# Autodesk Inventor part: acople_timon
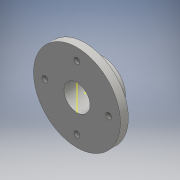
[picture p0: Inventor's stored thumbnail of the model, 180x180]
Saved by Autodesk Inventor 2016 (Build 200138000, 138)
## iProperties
Created: 2017-06
Part Number: acople_timon
Material: Generic
Document SubType Name: Modeling
Designer: laboratorioesan
Density: 1 g/cm^3
Appearance: Default
Author: laboratorioesan
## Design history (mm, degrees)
sketch "Sketch1"
  geometry: C1 r 9 at (0, 0); C2 r 15.5 at (0, 0); 1 further point
  constraints: 2 centre point, 2 coincident
  dimensions: "d0" = 18 diameter of C1; "d1" = 31 diameter of C2
extrude "Extrusion1" new body sketch "Sketch1" distance "d2" = 12.5; taper "d3" = 0 deg
sketch "Sketch2"
  geometry: C1 r 9 at (0, 0) reference; C2 r 15.5 at (0, 0) reference; C3 r 30 at (0, 0); 1 further point
  constraints: 1 centre point, 1 coincident
  dimensions: "d4" = 60 diameter of C3
extrude "Extrusion2" join sketch "Sketch2" distance "d5" = 5.5; taper "d6" = 0 deg
sketch "Sketch3"
  geometry: L1 (-5.5, -9)-(-5.5, 9) reference; L2 (12.5, 9)-(12.5, -9) reference; 1 further point
  node "Projected Loop2"
sketch "Sketch4"
  geometry: C1 r 30 at (0, 0) reference; C2 r 15.5 at (0, 0) reference; C3 r 2 at (0, 22); C4 r 2 at (-22, 0); C5 r 2 at (0, -22); C6 r 2 at (22, 0); 1 further point
  constraints: 4 centre point, 9 other
  dimensions: "d7" = 4 diameter of C3; "d8" = 22 distance of point (0, 0) C3.centre; "d11" = 360 deg dimension on C1.centre C3.centre (derived)
extrude "Extrusion3" cut sketch "Sketch4" distance "d13" = 10; taper "d14" = 0 deg
body "Solid1"
node "Projected Loop1"
node "Projected Loop3"
